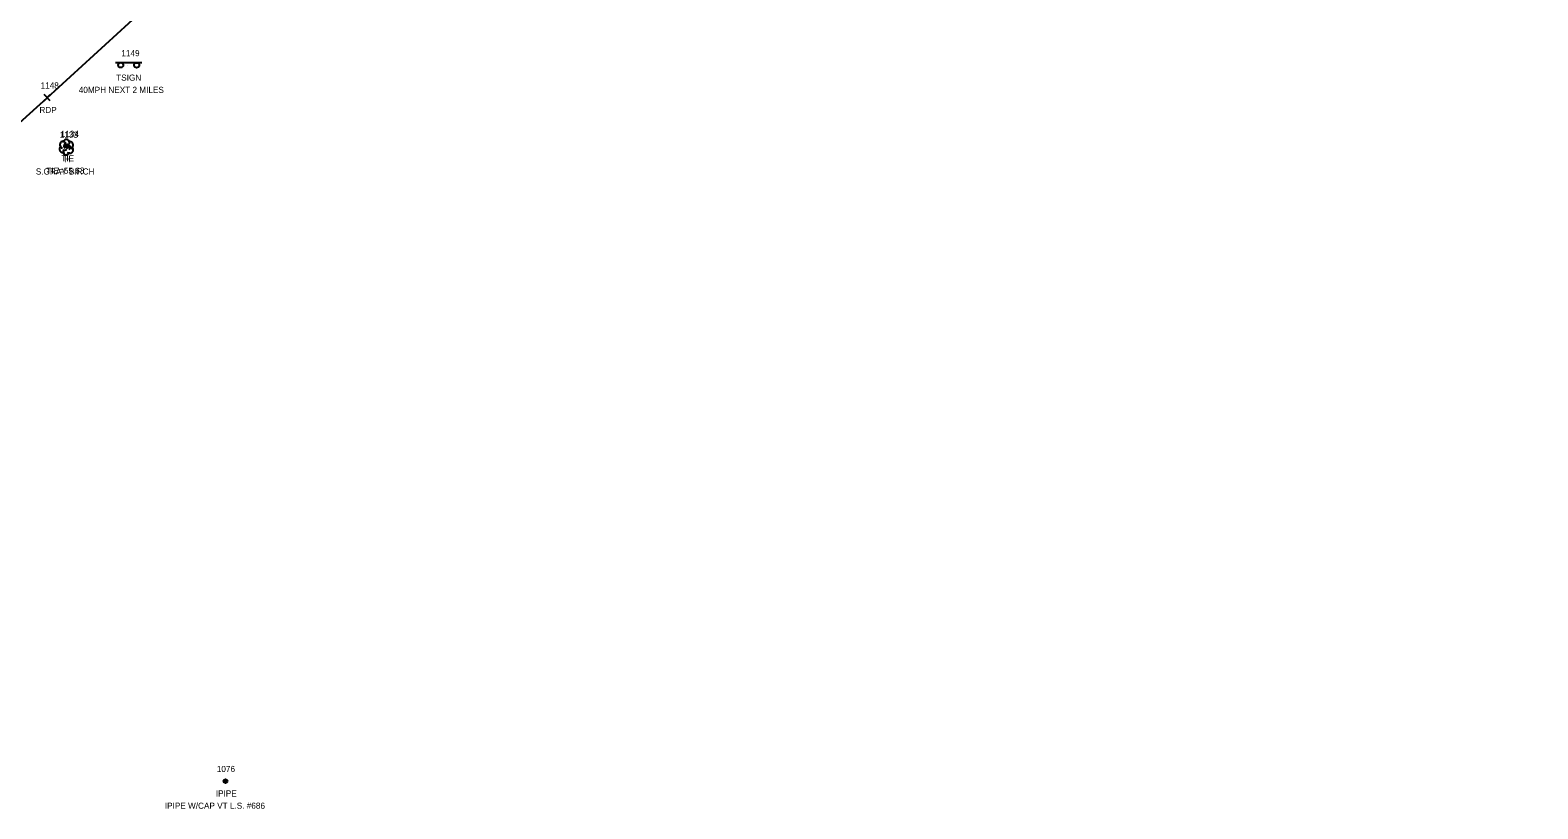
# Model space of a CAD drawing. Extents: x 1496556 to 1498241, y 599216 to 604470.
# Drawn here: x 1497547.4 to 1498039.7, y 602999.7 to 603254 of the extents above; entities that cross this region are included whole.
import ezdxf

# ---------------------------------------------------------------- set-up
doc = ezdxf.new("R2010")
doc.units = 0
for name, color, linetype in [('C_A', 7, 'Continuous'), ('C_C', 7, 'Continuous'), ('C_I', 7, 'Continuous'), ('CBP', 7, 'Continuous'), ('L_A', 7, 'Continuous'), ('L_C', 7, 'Continuous'), ('L_I', 7, 'Continuous'), ('LTD', 7, 'Continuous'), ('M_A', 7, 'Continuous'), ('M_C', 7, 'Continuous'), ('M_I', 7, 'Continuous'), ('MPIP', 7, 'Continuous'), ('P_A', 7, 'Continuous'), ('P_I', 7, 'Continuous'), ('P_TIC', 7, 'Continuous'), ('PET', 7, 'Continuous'), ('S_A', 7, 'Continuous'), ('S_C', 7, 'Continuous'), ('S_I', 7, 'Continuous'), ('SSGN', 7, 'Continuous')]:
    doc.layers.add(name, color=color, linetype=linetype)

msp = doc.modelspace()

# ---------------------------------------------------------------- linework, layer by layer
at = {"layer": 'CBP'}
for radius in [0.625, 0.0833]:
    msp.add_circle((1497559.52, 603216.16), radius, dxfattribs=at)
at = {"layer": 'LTD'}
msp.add_line((1497559.21, 603215.88), (1497559.21, 603215.88), dxfattribs=at)
msp.add_line((1497559.21, 603215.88), (1497559.21, 603215.88), dxfattribs=at)
msp.add_arc((1497559.26, 603217.31), 1.05, 335.5272, 180.9563, dxfattribs=at)
for centre, major_axis, ratio, start_param, end_param in [((1497558.13, 603215.17), (0.58, -1.04), 0.959034, 3.141593, 6.283185), ((1497558.42, 603216.54), (1.21, -0.51), 0.895232, 1.570796, 4.712389), ((1497559.21, 603214.38), (0.26, 1.06), 0.942809, 1.570796, 4.712389), ((1497558.75, 603215.13), (-0.625, -0.083), 0.423636, 0, 3.141593), ((1497559, 603216.33), (-0.208, -0.792), 0.645439, 3.141593, 6.283185), ((1497559.71, 603215.71), (-0.5, 0.667), 0.989748, 3.141593, 6.283185), ((1497560.21, 603215.04), (-1.09, 0.79), 0.841452, 1.570796, 4.712389), ((1497560.25, 603216.46), (-1.14, -0.48), 0.949671, 1.570796, 4.712389)]:
    msp.add_ellipse(centre, major_axis=major_axis, ratio=ratio, start_param=start_param, end_param=end_param, dxfattribs=at)
at = {"layer": 'MPIP'}
for radius in [0.625, 0.0833]:
    msp.add_circle((1497611.2, 603008.77), radius, dxfattribs=at)
at = {"layer": 'P_TIC'}
for points in [[(1497551.95, 603230.97), (1497553.95, 603232.97)], [(1497553.95, 603230.97), (1497551.95, 603232.97)]]:
    msp.add_lwpolyline(points, dxfattribs=at)
at = {"layer": 'PET'}
msp.add_lwpolyline([(1497522.29, 603204.31), (1497552.95, 603231.97), (1497591.08, 603266.91), (1497627.26, 603299.53), (1497662.95, 603331.45), (1497697.84, 603363.51), (1497746.34, 603407.32), (1497759.4, 603419.2), (1497780.77, 603438.17), (1497814.38, 603468.18), (1497842.75, 603493.95), (1497876.67, 603525.23), (1497903.96, 603551.93), (1497933.62, 603583.71), (1497962.05, 603618.46), (1497981.16, 603645.77), (1498004.55, 603682.86), (1498024.5, 603720), (1498039.75, 603752.79)], dxfattribs=at)
at = {"layer": 'SSGN'}
for p, q in [((1497575.33, 603243.45), (1497583.92, 603243.45)), ((1497579.35, 603242.55), (1497579.35, 603242.55))]:
    msp.add_line(p, q, dxfattribs=at)
for centre in [(1497576.99, 603242.62), (1497582.2, 603242.55)]:
    msp.add_circle(centre, 0.833, dxfattribs=at)

# ---------------------------------------------------------------- texts
at = {"layer": 'C_A'}
msp.add_text('TIE', height=2, dxfattribs=at).set_placement((1497557.6, 603211.16))
at = {"layer": 'C_C'}
msp.add_text('TIE=55.63', height=2, dxfattribs=at).set_placement((1497552.7, 603207.16))
at = {"layer": 'C_I'}
msp.add_text('1134', height=2, dxfattribs=at).set_placement((1497557.4, 603219.16))
at = {"layer": 'L_A'}
msp.add_text('H', height=2, dxfattribs=at).set_placement((1497558.65, 603210.88))
at = {"layer": 'L_C'}
msp.add_text('S.GRAY BIRCH', height=2, dxfattribs=at).set_placement((1497549.26, 603206.88))
at = {"layer": 'L_I'}
msp.add_text('1133', height=2, dxfattribs=at).set_placement((1497557.09, 603218.88))
at = {"layer": 'M_A'}
msp.add_text('IPIPE', height=2, dxfattribs=at).set_placement((1497608.04, 603003.77))
at = {"layer": 'M_C'}
msp.add_text('IPIPE W/CAP VT L.S. #686', height=2, dxfattribs=at).set_placement((1497591.4, 602999.77))
at = {"layer": 'M_I'}
msp.add_text('1076', height=2, dxfattribs=at).set_placement((1497608.37, 603011.77))
at = {"layer": 'P_A'}
msp.add_text('RDP', height=2, dxfattribs=at).set_placement((1497550.44, 603226.97))
at = {"layer": 'P_I'}
msp.add_text('1148', height=2, dxfattribs=at).set_placement((1497550.83, 603234.97))
at = {"layer": 'S_A'}
msp.add_text('TSIGN', height=2, dxfattribs=at).set_placement((1497575.52, 603237.53))
at = {"layer": 'S_C'}
msp.add_text('40MPH NEXT 2 MILES', height=2, dxfattribs=at).set_placement((1497563.3, 603233.53))
at = {"layer": 'S_I'}
msp.add_text('1149', height=2, dxfattribs=at).set_placement((1497577.21, 603245.53))

doc.saveas('drawing.dxf')
